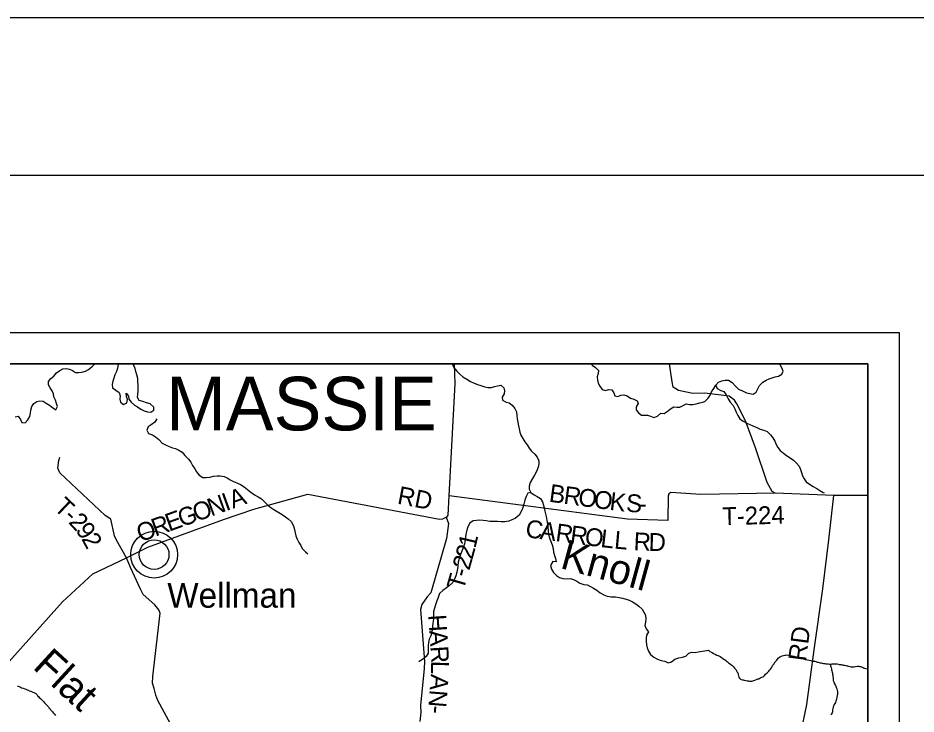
# Model space of a CAD drawing. Extents: x 0.4 to 34.4, y -2.1 to 19.9.
# Drawn here: x 7.097 to 9.953, y 17.722 to 19.936 of the extents above; entities that cross this region are included whole.
import ezdxf

# ---------------------------------------------------------------- set-up
doc = ezdxf.new("R2010")
doc.units = 0
for name, color, linetype in [('GM_X_County', 7, 'Continuous'), ('GM_X_County_Road', 7, 'Continuous'), ('GM_X_County_Road_Text', 7, 'Continuous'), ('GM_X_Major_Lake', 7, 'Continuous'), ('GM_X_Minor_River', 7, 'Continuous'), ('GM_X_Minor_River_Text', 7, 'Continuous'), ('GM_X_Township', 7, 'Continuous'), ('GM_X_Township_Road', 7, 'Continuous'), ('GM_X_Township_Road_Text', 7, 'Continuous'), ('GM_X_Township_Text', 7, 'Continuous'), ('GM_X_Unincorporated', 7, 'Continuous'), ('GM_X_Unincorporated_Text', 7, 'Continuous'), ('SH_Border', 7, 'Continuous'), ('SH_Cut_Line', 7, 'Continuous'), ('SH_Data', 7, 'Continuous')]:
    doc.layers.add(name, color=color, linetype=linetype)

msp = doc.modelspace()

# ---------------------------------------------------------------- linework, layer by layer
at = {"layer": 'GM_X_County'}
msp.add_lwpolyline([(9.8001, 15.3423), (9.8001, 18.8357), (3.0001, 18.8357), (3.0001, 12.0357), (9.5074, 12.0357)], dxfattribs=at)
at = {"layer": 'GM_X_County_Road'}
for points in [[(7.032, 17.8492), (7.2391, 18.0795), (7.3349, 18.1676), (7.4418, 18.2194), (7.5103, 18.2534), (7.7506, 18.3404), (7.8469, 18.3742), (8.0189, 18.4219), (8.4374, 18.342), (8.448, 18.3429), (8.459, 18.3478), (8.4611, 18.3487), (8.4653, 18.3547), (8.4684, 18.4161), (8.487, 18.7738), (8.4853, 18.8331), (8.4858, 18.8357)], [(9.6917, 18.417), (9.5047, 18.4243), (9.4952, 18.4296), (9.4795, 18.4585), (9.4422, 18.5683), (9.4113, 18.6542), (9.3834, 18.7085), (9.376, 18.7204), (9.3584, 18.7332), (9.282, 18.743), (9.2432, 18.7417), (9.1976, 18.7508), (9.1807, 18.7618), (9.1772, 18.7782), (9.1696, 18.8357)], [(9.5854, 17.6546), (9.6059, 17.7522), (9.6295, 17.9264), (9.6572, 18.1203), (9.6759, 18.2757), (9.6917, 18.417)], [(7.7137, 17.448), (7.5422, 17.7657), (7.535, 17.7826), (7.5305, 17.8035), (7.5251, 17.8203), (7.5259, 17.8419), (7.5495, 18.0433), (7.5452, 18.0536), (7.5322, 18.0694), (7.4953, 18.1027), (7.4872, 18.1192), (7.4552, 18.1881), (7.4418, 18.2194)]]:
    msp.add_lwpolyline(points, dxfattribs=at)
at = {"layer": 'GM_X_Major_Lake'}
for points in [[(7.3216, 18.8176), (7.3323, 18.8261), (7.3418, 18.8357)], [(7.4154, 18.8357), (7.4152, 18.8339), (7.4135, 18.8226), (7.4099, 18.8116), (7.4056, 18.8011), (7.4024, 18.7902), (7.3992, 18.7803), (7.3967, 18.7698), (7.3981, 18.7595), (7.4086, 18.7521), (7.4187, 18.7444), (7.4224, 18.7341), (7.4211, 18.7239), (7.4232, 18.7136), (7.4329, 18.7066), (7.4429, 18.7114), (7.4449, 18.722), (7.4417, 18.7319), (7.4411, 18.7422), (7.4481, 18.7326), (7.4495, 18.7231), (7.457, 18.7135), (7.4671, 18.7046), (7.4768, 18.6987), (7.4877, 18.6914), (7.4987, 18.6859), (7.5085, 18.6831), (7.5198, 18.6818), (7.5294, 18.6884), (7.5288, 18.6979), (7.5172, 18.7084), (7.5055, 18.7119), (7.4942, 18.7159), (7.4825, 18.7188), (7.4769, 18.7291), (7.4782, 18.7393), (7.4791, 18.7491), (7.4793, 18.7594), (7.4791, 18.7689), (7.4785, 18.7787), (7.4783, 18.7897), (7.4754, 18.8004), (7.4721, 18.8111), (7.4696, 18.8206), (7.4652, 18.8301), (7.4635, 18.8357)], [(7.0884, 18.6669), (7.098, 18.6694), (7.1046, 18.659), (7.109, 18.6491), (7.12, 18.6482), (7.1285, 18.6579), (7.1351, 18.6684), (7.1364, 18.679), (7.1374, 18.6889), (7.1409, 18.6998), (7.1472, 18.7099), (7.1571, 18.7162), (7.1667, 18.7187), (7.1769, 18.7171), (7.187, 18.7105), (7.1976, 18.7039), (7.2073, 18.6965), (7.2171, 18.6891), (7.2229, 18.6997), (7.2197, 18.7096), (7.2164, 18.7199), (7.2113, 18.7306), (7.2099, 18.7401), (7.2059, 18.7496), (7.1992, 18.7599), (7.1944, 18.7695), (7.1938, 18.7794), (7.2012, 18.7895), (7.2108, 18.7969), (7.22, 18.807), (7.23, 18.8148), (7.24, 18.82), (7.2506, 18.8206), (7.2605, 18.8193), (7.2703, 18.8142), (7.2804, 18.8087), (7.2907, 18.8082), (7.3005, 18.8092), (7.312, 18.8124), (7.3216, 18.8176)]]:
    msp.add_lwpolyline(points, dxfattribs=at)
at = {"layer": 'GM_X_Minor_River'}
for points in [[(8.4785, 18.8357), (8.4787, 18.8333), (8.4835, 18.8237), (8.4928, 18.8122), (8.5018, 18.8026), (8.5123, 18.7945), (8.5247, 18.7875), (8.5359, 18.7797), (8.5461, 18.775), (8.559, 18.7706), (8.5695, 18.767), (8.582, 18.7631), (8.5918, 18.7606), (8.6032, 18.7608), (8.6127, 18.7633), (8.6226, 18.7655), (8.6329, 18.7679), (8.6427, 18.7595), (8.6444, 18.7499), (8.6431, 18.7401), (8.6365, 18.7296), (8.6383, 18.7201), (8.6492, 18.7142), (8.659, 18.7114), (8.6691, 18.7048), (8.6769, 18.6941), (8.6821, 18.683), (8.6838, 18.6716), (8.6844, 18.6606), (8.6869, 18.6499), (8.6894, 18.6389), (8.6911, 18.6294), (8.6936, 18.6184), (8.6965, 18.6088), (8.7024, 18.5985), (8.7095, 18.5878), (8.7161, 18.5778), (8.7224, 18.5682), (8.7303, 18.5586), (8.7407, 18.549), (8.7486, 18.5394), (8.7533, 18.5279), (8.7535, 18.5177), (8.7515, 18.5071), (8.7463, 18.4939), (8.7401, 18.4823), (8.7331, 18.471), (8.726, 18.4586), (8.7228, 18.4469), (8.723, 18.437), (8.7286, 18.4267), (8.7387, 18.4193), (8.7485, 18.4143), (8.7587, 18.408), (8.7657, 18.3973), (8.7682, 18.3867), (8.7707, 18.3768), (8.7724, 18.3672), (8.7764, 18.3505), (8.7788, 18.3376), (8.7813, 18.3265), (8.7819, 18.3152), (8.7829, 18.3057), (8.7846, 18.2927), (8.7878, 18.2821), (8.7914, 18.2714), (8.7962, 18.2599), (8.7991, 18.2489), (8.8004, 18.2375), (8.8037, 18.2268), (8.8069, 18.2166), (8.8083, 18.2063), (8.798, 18.2068), (8.7906, 18.1941), (8.7935, 18.1826), (8.8002, 18.1723)], [(8.921, 18.8357), (8.9232, 18.8321), (8.9333, 18.8239), (8.943, 18.8151), (8.9425, 18.8056), (8.9393, 18.7946), (8.9399, 18.7844), (8.9428, 18.7745), (8.9479, 18.7649), (8.9546, 18.7542), (8.9655, 18.7514), (8.9762, 18.7543), (8.9857, 18.7537), (8.9924, 18.7441), (8.9949, 18.7339), (9.0051, 18.7322), (9.0147, 18.7366), (9.0242, 18.7372), (9.0344, 18.7336), (9.0456, 18.7266), (9.0558, 18.7231), (9.066, 18.7187), (9.07, 18.7092), (9.0634, 18.6991), (9.0633, 18.6892), (9.0703, 18.6796), (9.0801, 18.6726), (9.0896, 18.6725), (9.0991, 18.6723), (9.1089, 18.6699), (9.1191, 18.6652), (9.1309, 18.6699), (9.142, 18.6785), (9.1519, 18.678), (9.1615, 18.6839), (9.1723, 18.6932), (9.183, 18.6991), (9.1928, 18.6978), (9.2023, 18.6984), (9.2123, 18.7036), (9.2222, 18.7091), (9.2324, 18.7063), (9.2431, 18.7065), (9.2541, 18.709), (9.2652, 18.7118), (9.2751, 18.714), (9.2816, 18.7161)], [(9.2816, 18.7161), (9.2917, 18.7265), (9.2983, 18.7366), (9.3031, 18.7468), (9.3097, 18.7572), (9.316, 18.7677), (9.3249, 18.7774), (9.3356, 18.7814), (9.3459, 18.7834), (9.3565, 18.7836), (9.3689, 18.7765), (9.3777, 18.7657), (9.3885, 18.7556), (9.4017, 18.75), (9.414, 18.7437), (9.425, 18.7412), (9.4348, 18.7399), (9.4444, 18.7454), (9.4499, 18.7559), (9.4558, 18.7671), (9.4663, 18.7779), (9.4762, 18.7842), (9.4858, 18.7878), (9.4957, 18.7914), (9.5052, 18.7942), (9.5155, 18.797), (9.5262, 18.8025), (9.5306, 18.8123), (9.5263, 18.823), (9.5208, 18.833), (9.5203, 18.8357)], [(9.316, 18.7677), (9.3211, 18.7578), (9.3324, 18.7515), (9.3421, 18.7475), (9.3495, 18.7375), (9.3557, 18.7248), (9.3623, 18.7144), (9.3719, 18.7032), (9.377, 18.6929), (9.3817, 18.6822), (9.3864, 18.6718), (9.393, 18.6611), (9.4035, 18.6537), (9.4151, 18.647), (9.4248, 18.643), (9.4346, 18.6386), (9.447, 18.6334), (9.4579, 18.6283), (9.4688, 18.6254), (9.4797, 18.6202), (9.4901, 18.6105), (9.4982, 18.6009), (9.5037, 18.5902), (9.508, 18.5798), (9.5135, 18.5698), (9.5209, 18.5602), (9.5317, 18.5513), (9.5418, 18.5442), (9.5534, 18.5368), (9.5631, 18.5298), (9.5727, 18.5205), (9.5812, 18.51), (9.5856, 18.5001), (9.5892, 18.4905), (9.5924, 18.4798), (9.5971, 18.4703), (9.6041, 18.4606), (9.6149, 18.4532), (9.6265, 18.4461), (9.6381, 18.4391), (9.6478, 18.4328), (9.6579, 18.4269), (9.6606, 18.4261)], [(7.5389, 18.6606), (7.5326, 18.6501), (7.5211, 18.6416), (7.5108, 18.6353), (7.5068, 18.6251), (7.512, 18.6144), (7.5244, 18.6097), (7.5346, 18.6042), (7.5451, 18.5949), (7.5555, 18.5838), (7.5679, 18.5771), (7.5777, 18.5732), (7.5887, 18.5688), (7.5985, 18.5664), (7.6091, 18.5617), (7.6188, 18.5551), (7.6278, 18.5447), (7.639, 18.5332), (7.6464, 18.5228), (7.6523, 18.5121), (7.6594, 18.5021), (7.6653, 18.4926), (7.6731, 18.4822), (7.6848, 18.4748), (7.6954, 18.4739), (7.7072, 18.4756), (7.7194, 18.4784), (7.7308, 18.4798), (7.7403, 18.48), (7.7524, 18.4776), (7.7622, 18.4729), (7.7723, 18.467), (7.7829, 18.4619), (7.7934, 18.4576), (7.8047, 18.4521), (7.8164, 18.4447), (7.8273, 18.4366), (7.8378, 18.4273), (7.849, 18.4196), (7.8611, 18.4129), (7.8712, 18.4067), (7.8813, 18.3971), (7.8906, 18.3874), (7.9008, 18.3793), (7.9105, 18.3731), (7.9211, 18.3665), (7.932, 18.3602), (7.944, 18.3529), (7.956, 18.3432), (7.9657, 18.3343), (7.9735, 18.3202), (7.976, 18.3091), (7.9785, 18.2988), (7.981, 18.2889), (7.9846, 18.2783), (7.9905, 18.2676), (7.9964, 18.258), (8.0012, 18.2484), (8.0117, 18.2377), (8.0192, 18.2319)], [(8.7286, 18.4267), (8.7187, 18.4246), (8.7132, 18.4144), (8.7092, 18.402), (8.7056, 18.3891), (8.7012, 18.3763), (8.6969, 18.3658), (8.6906, 18.3545), (8.6787, 18.3444), (8.668, 18.3401), (8.6581, 18.336), (8.6459, 18.3336), (8.6341, 18.3338), (8.622, 18.3347), (8.6095, 18.3341), (8.5977, 18.3343), (8.5864, 18.3364), (8.5765, 18.3381), (8.5647, 18.3383), (8.5552, 18.3376), (8.545, 18.3363), (8.5346, 18.3289), (8.5276, 18.318), (8.5244, 18.307), (8.5216, 18.2946), (8.5199, 18.2843), (8.5197, 18.2749), (8.5173, 18.2632), (8.5129, 18.2507), (8.5082, 18.2405), (8.5042, 18.2292), (8.4998, 18.2164), (8.497, 18.2051), (8.4957, 18.1937), (8.4948, 18.1839), (8.4927, 18.1729), (8.4891, 18.1616), (8.4855, 18.1514), (8.4797, 18.1405), (8.4697, 18.1308), (8.4601, 18.1237), (8.4486, 18.1156), (8.4381, 18.1055), (8.433, 18.0931), (8.4294, 18.0821), (8.4254, 18.0693), (8.4218, 18.0584), (8.419, 18.0485), (8.4181, 18.0368), (8.4187, 18.0235), (8.4166, 18.011), (8.4153, 18.0012), (8.4147, 17.9917), (8.4134, 17.9819), (8.4102, 17.9706), (8.4051, 17.9604), (8.4023, 17.9495), (8.4014, 17.9392), (8.4016, 17.9252), (8.4018, 17.9157), (8.3948, 17.9048), (8.3836, 17.8959), (8.3733, 17.8892), (8.3718, 17.8884)], [(8.8002, 18.1723), (8.8095, 18.1623), (8.8196, 18.1561), (8.8302, 18.1532), (8.842, 18.1527), (8.8541, 18.1529), (8.8643, 18.1504), (8.8741, 18.1446), (8.8839, 18.138), (8.8971, 18.134), (8.9077, 18.1327), (8.9175, 18.128), (8.9277, 18.1221), (8.9378, 18.1159), (8.9487, 18.1074), (8.9607, 18.1015), (8.9709, 18.0968), (8.9834, 18.0951), (8.9974, 18.0945), (9.0092, 18.0932), (9.0198, 18.0911), (9.0311, 18.0879), (9.0413, 18.0844), (9.0515, 18.0793), (9.062, 18.073), (9.0721, 18.0649), (9.0819, 18.056), (9.0878, 18.0465), (9.0933, 18.0369), (9.0943, 18.0255), (9.0926, 18.0145), (9.0902, 18.0036), (9.0946, 17.9937), (9.102, 17.9833), (9.0958, 17.9735), (9.0949, 17.9633), (9.0951, 17.9538), (9.0964, 17.9428), (9.0982, 17.9326), (9.1022, 17.9219), (9.1092, 17.9119), (9.119, 17.9026), (9.1306, 17.8964), (9.1431, 17.8928), (9.1544, 17.89), (9.1654, 17.8849), (9.1757, 17.8885), (9.1864, 17.8963), (9.1986, 17.9014), (9.2101, 17.9035), (9.2207, 17.9068), (9.2308, 17.9157), (9.2407, 17.9193), (9.2509, 17.9184), (9.2606, 17.9204)], [(9.2606, 17.9204), (9.2927, 17.9251), (9.2953, 17.9235), (9.2979, 17.9212), (9.3032, 17.9185), (9.3077, 17.9158), (9.3103, 17.9142), (9.3149, 17.9122), (9.3198, 17.9099), (9.3224, 17.9087), (9.3262, 17.9072), (9.33, 17.9048), (9.3345, 17.9025), (9.3382, 17.8998), (9.3416, 17.8971), (9.3443, 17.8955), (9.3469, 17.8932), (9.3506, 17.8901), (9.3536, 17.8878), (9.3566, 17.8855), (9.3596, 17.8831), (9.3642, 17.8797), (9.3672, 17.8773), (9.3705, 17.8746), (9.3728, 17.8719), (9.3758, 17.8685), (9.3788, 17.8654), (9.3814, 17.8623), (9.3825, 17.8597), (9.3847, 17.8555), (9.3862, 17.8528), (9.388, 17.8482), (9.3891, 17.8436), (9.3902, 17.8394), (9.3913, 17.836), (9.3954, 17.8329), (9.4007, 17.8313), (9.4037, 17.8305), (9.4071, 17.8297), (9.4117, 17.8289), (9.4158, 17.8281), (9.4204, 17.8276), (9.4234, 17.8272), (9.4261, 17.8268), (9.4306, 17.8271), (9.4344, 17.8282), (9.4375, 17.8289), (9.4405, 17.83), (9.4459, 17.8318), (9.4505, 17.8337), (9.4535, 17.8347), (9.4566, 17.8362), (9.4596, 17.8381), (9.4627, 17.8396), (9.4661, 17.841), (9.4688, 17.8425), (9.4727, 17.8462), (9.475, 17.8493), (9.4796, 17.8537), (9.485, 17.859), (9.4873, 17.862), (9.4908, 17.8654), (9.4931, 17.8687), (9.4955, 17.8736), (9.497, 17.8763), (9.5009, 17.8812), (9.5051, 17.8879), (9.5102, 17.8939), (9.5152, 17.8999), (9.5198, 17.9037), (9.5229, 17.9052), (9.5271, 17.9074), (9.5313, 17.9088), (9.5358, 17.9099), (9.5385, 17.9099), (9.5427, 17.9102), (9.548, 17.9094), (9.5521, 17.9085), (9.5559, 17.9077), (9.5586, 17.9073), (9.5612, 17.9065), (9.5643, 17.9061), (9.5673, 17.9053), (9.5718, 17.9041), (9.5745, 17.9033), (9.5783, 17.9021), (9.5813, 17.9013), (9.5843, 17.9005), (9.5877, 17.8997), (9.5911, 17.8985), (9.5957, 17.8973), (9.6002, 17.8961), (9.6036, 17.8953)], [(9.6036, 17.8953), (9.6081, 17.8945), (9.6131, 17.8936), (9.6184, 17.8924), (9.6214, 17.8916), (9.6252, 17.8908), (9.6309, 17.8903), (9.635, 17.8888), (9.6392, 17.8876), (9.6418, 17.8872), (9.6449, 17.8864), (9.6483, 17.8855), (9.6517, 17.8847), (9.6547, 17.8839), (9.6589, 17.8831), (9.6627, 17.8827), (9.6664, 17.8823), (9.6691, 17.8818), (9.674, 17.8818), (9.6782, 17.8813), (9.6809, 17.8813), (9.685, 17.8816), (9.6881, 17.8816), (9.6907, 17.8815), (9.6957, 17.8815), (9.6995, 17.8814), (9.7021, 17.8814), (9.7063, 17.8806), (9.7089, 17.8801), (9.7116, 17.8797), (9.7146, 17.8793), (9.7177, 17.8789), (9.7203, 17.8785), (9.723, 17.878), (9.7256, 17.8772), (9.7302, 17.8764), (9.7328, 17.8756), (9.7355, 17.8752), (9.7381, 17.8744), (9.7427, 17.8736), (9.7457, 17.8728), (9.7491, 17.872), (9.7536, 17.8723), (9.7563, 17.8726), (9.7605, 17.8733), (9.7666, 17.8744), (9.7711, 17.874), (9.7738, 17.8735), (9.7764, 17.8731), (9.7829, 17.8708), (9.7859, 17.8692), (9.7893, 17.868), (9.7934, 17.8668), (9.7976, 17.8656), (9.8001, 17.8648)], [(9.6809, 17.8813), (9.6808, 17.8752), (9.6819, 17.8725), (9.683, 17.8699), (9.6841, 17.8657), (9.6848, 17.8626), (9.6859, 17.8596), (9.687, 17.8554), (9.6873, 17.8527), (9.688, 17.8489), (9.6887, 17.8455), (9.6887, 17.8417), (9.6893, 17.8368), (9.6893, 17.8341), (9.6896, 17.8311), (9.69, 17.8284), (9.6915, 17.8246), (9.6925, 17.8211), (9.694, 17.8181), (9.6966, 17.8131), (9.6977, 17.8104), (9.6992, 17.8074), (9.6999, 17.8047), (9.701, 17.802), (9.7021, 17.7979), (9.7032, 17.7929), (9.7035, 17.7883), (9.703, 17.7849), (9.7026, 17.7808), (9.7018, 17.7758), (9.6998, 17.7698), (9.6994, 17.7668), (9.6986, 17.7634), (9.697, 17.7592), (9.6954, 17.7554), (9.6931, 17.7524), (9.6915, 17.7498), (9.6904, 17.7471), (9.6895, 17.7441), (9.6884, 17.74), (9.6879, 17.7358), (9.6875, 17.7324), (9.6871, 17.729), (9.6863, 17.7263), (9.6843, 17.7226), (9.6827, 17.7192)], [(7.0953, 17.8112), (7.098, 17.8104), (7.101, 17.8096), (7.1051, 17.808), (7.1085, 17.8057), (7.1138, 17.8041), (7.1184, 17.8021), (7.1218, 17.8009), (7.1259, 17.7993), (7.1301, 17.7977), (7.1327, 17.7961), (7.1376, 17.7945), (7.1418, 17.7929), (7.1444, 17.7921), (7.1475, 17.7909), (7.1501, 17.7897), (7.1535, 17.7877), (7.158, 17.7838), (7.1594, 17.7804), (7.1624, 17.7781), (7.1639, 17.775), (7.1688, 17.7715), (7.1721, 17.768), (7.1751, 17.7653), (7.1777, 17.7618), (7.1814, 17.7583), (7.1855, 17.7541), (7.1877, 17.7513), (7.1907, 17.7482), (7.1937, 17.7448), (7.1967, 17.7413), (7.1989, 17.7386), (7.2015, 17.7351), (7.2033, 17.732), (7.2063, 17.7293), (7.2089, 17.7259), (7.2123, 17.7227), (7.216, 17.7181)]]:
    msp.add_lwpolyline(points, dxfattribs=at)
at = {"layer": 'GM_X_Township'}
msp.add_lwpolyline([(9.8001, 15.535), (9.8001, 18.8357), (6.992, 18.8357)], dxfattribs=at)
at = {"layer": 'GM_X_Township_Road'}
for points in [[(7.4418, 18.2194), (7.4106, 18.2756), (7.4043, 18.2893), (7.3921, 18.3415), (7.3744, 18.3538), (7.2301, 18.4896), (7.2238, 18.504), (7.2271, 18.5283), (7.2299, 18.5396)], [(9.5047, 18.4243), (9.2686, 18.42), (9.1731, 18.4269), (9.1666, 18.4224), (9.1653, 18.4148), (9.164, 18.3378), (9.0355, 18.3416), (8.4684, 18.4161)], [(9.8001, 18.4169), (9.6917, 18.417)], [(8.459, 18.3478), (8.4664, 18.3277), (8.4597, 18.2803), (8.4098, 18.1079), (8.3987, 18.0951), (8.3817, 18.071), (8.3773, 18.0547), (8.3897, 17.8891), (8.3894, 17.8671), (8.3777, 17.7496), (8.3782, 17.7268), (8.3756, 17.6984)]]:
    msp.add_lwpolyline(points, dxfattribs=at)
at = {"layer": 'GM_X_Unincorporated'}
for radius in [0.0744, 0.0472]:
    msp.add_circle((7.5301, 18.2291), radius, dxfattribs=at)
at = {"layer": 'SH_Border'}
msp.add_lwpolyline([(2.4001, 19.4357), (33.9001, 19.4357), (33.9001, -1.5643), (2.4001, -1.5643)], close=True, dxfattribs=at)
at = {"layer": 'SH_Cut_Line'}
msp.add_lwpolyline([(0.4001, -2.0643), (34.4001, -2.0643), (34.4001, 19.9357), (0.4001, 19.9357)], close=True, dxfattribs=at)
at = {"layer": 'SH_Data'}
for p, q in [((2.9001, 18.9357), (9.9001, 18.9357)), ((9.9001, 18.9357), (9.9001, 11.9357)), ((3.0001, 18.8357), (9.8001, 18.8357)), ((9.8001, 18.8357), (9.8001, 12.0357))]:
    msp.add_line(p, q, dxfattribs=at)

# ---------------------------------------------------------------- texts
at = {"layer": 'GM_X_County_Road_Text'}
for s, height, rotation, p in [('I', 0.0568, 19.8221, (7.7585, 18.3671)), ('A', 0.0568, 19.8197, (7.7805, 18.375)), ('RD', 0.05682, 349.0774, (8.3011, 18.3916)), ('O', 0.0568, 19.8197, (7.6645, 18.3331)), ('N', 0.0568, 19.8197, (7.7115, 18.3501)), ('E', 0.0568, 19.8202, (7.5774, 18.3018)), ('G', 0.0568, 19.8197, (7.6174, 18.3162)), ('R', 0.0568, 19.8507, (7.5336, 18.2859)), ('O', 0.0568, 21.3955, (7.4874, 18.2678)), ('RD', 0.05682, 82.569, (9.603, 17.8883))]:
    msp.add_text(s, height=height, rotation=rotation, dxfattribs=at).set_placement(p)
at = {"layer": 'GM_X_Minor_River_Text'}
for s, rotation, p in [('Knoll', 344.675, (8.818, 18.1872)), ('Flat', 317.4995, (7.1406, 17.8691))]:
    msp.add_text(s, height=0.09469, rotation=rotation, dxfattribs=at).set_placement(p)
at = {"layer": 'GM_X_Township_Road_Text'}
for s, height, rotation, p in [('B', 0.0568, 352.3429, (8.784, 18.3976)), ('R', 0.0568, 352.3427, (8.8303, 18.3914)), ('O', 0.0568, 352.3434, (8.8765, 18.3852)), ('O', 0.0568, 352.3434, (8.9261, 18.3785)), ('K', 0.0568, 353.2295, (8.9766, 18.3717)), ('T', 0.0568, 316.4442, (7.2086, 18.3753)), ('S', 0.0568, 356.6812, (9.03, 18.3655)), ('-', 0.0568, 359.1242, (9.0709, 18.3632)), ('T-224', 0.05682, 1.4032, (9.3376, 18.3227)), ('-', 0.0568, 316.4442, (7.2394, 18.3461)), ('2', 0.0568, 312.8327, (7.2556, 18.3307)), ('C', 0.0568, 352.4257, (8.7089, 18.2851)), ('9', 0.0568, 305.6096, (7.2782, 18.3065)), ('A', 0.0568, 352.4227, (8.7551, 18.2789)), ('R', 0.0568, 352.429, (8.8047, 18.2724)), ('R', 0.0568, 352.4329, (8.851, 18.2662)), ('O', 0.0568, 352.6472, (8.8974, 18.26)), ('L', 0.0568, 353.5296, (8.948, 18.2535)), ('2', 0.0568, 298.3865, (7.2976, 18.2796)), ('1', 0.0568, 77.0237, (8.5517, 18.2472)), ('L', 0.0568, 355.0439, (8.9918, 18.2486)), ('R', 0.0568, 357.4651, (9.0542, 18.2434)), ('D', 0.0568, 358.7126, (9.1022, 18.2413)), ('2', 0.0568, 74.8493, (8.542, 18.2112)), ('2', 0.0568, 74.2484, (8.5323, 18.1769)), ('T', 0.0568, 74.0581, (8.5142, 18.1134)), ('-', 0.0568, 74.1043, (8.5259, 18.1543)), ('H', 0.0568, 273.9045, (8.4017, 18.037)), ('A', 0.0568, 273.8936, (8.4051, 17.9871)), ('R', 0.0568, 273.6126, (8.4085, 17.9373)), ('L', 0.0568, 268.6241, (8.4114, 17.892)), ('A', 0.0568, 265.6756, (8.4104, 17.8503)), ('N', 0.0568, 265.5585, (8.4066, 17.8005)), ('-', 0.0568, 265.3109, (8.4028, 17.7507))]:
    msp.add_text(s, height=height, rotation=rotation, dxfattribs=at).set_placement(p)
at = {"layer": 'GM_X_Township_Text'}
msp.add_text('MASSIE', height=0.17045, rotation=0, dxfattribs=at).set_placement((7.5681, 18.6242))
at = {"layer": 'GM_X_Unincorporated_Text'}
msp.add_text('Wellman', height=0.07898, rotation=0, dxfattribs=at).set_placement((7.5719, 18.0604))

doc.saveas('drawing.dxf')
